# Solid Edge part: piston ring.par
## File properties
Author: Robert a Rhodes jr
Template: Normal.par
Last saved by: CADCIM
Revision: 10
Application: Solid Edge
Accuracy: 0.99
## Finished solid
Body 1: solid body, 6 faces, 12 edges, 8 vertices.
  Faces by surface: plane 4, cylinder 2
  Edges by curve: line 8, circle 4
Bounding box of the edges (mm): 94.000 x 94.000 x 3.000, from (-47, -47, -3) to (47, 47, 0).
Cylindrical faces by radius (mm): R43 x1, R47 x1
Planar faces by outward normal: +y 1, +z 1, -y 1, -z 1
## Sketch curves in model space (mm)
line (-28.0593, 0, 0) -> (-28.0593, -1, 0)
line (-28.0593, -1, 0) -> (-54.5597, -1, 0)
line (-54.5597, -1, 0) -> (-54.5597, 0, 0)
line (-54.5597, 0, 0) -> (-28.0593, 0, 0)
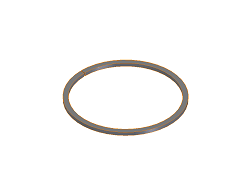
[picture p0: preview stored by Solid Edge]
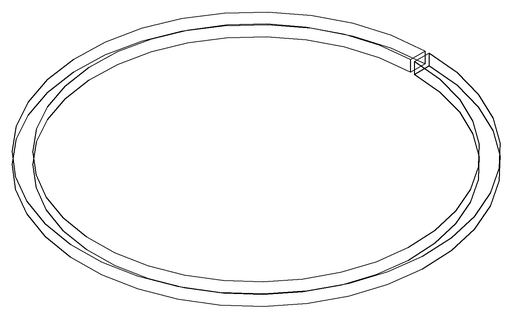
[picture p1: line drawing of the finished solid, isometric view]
